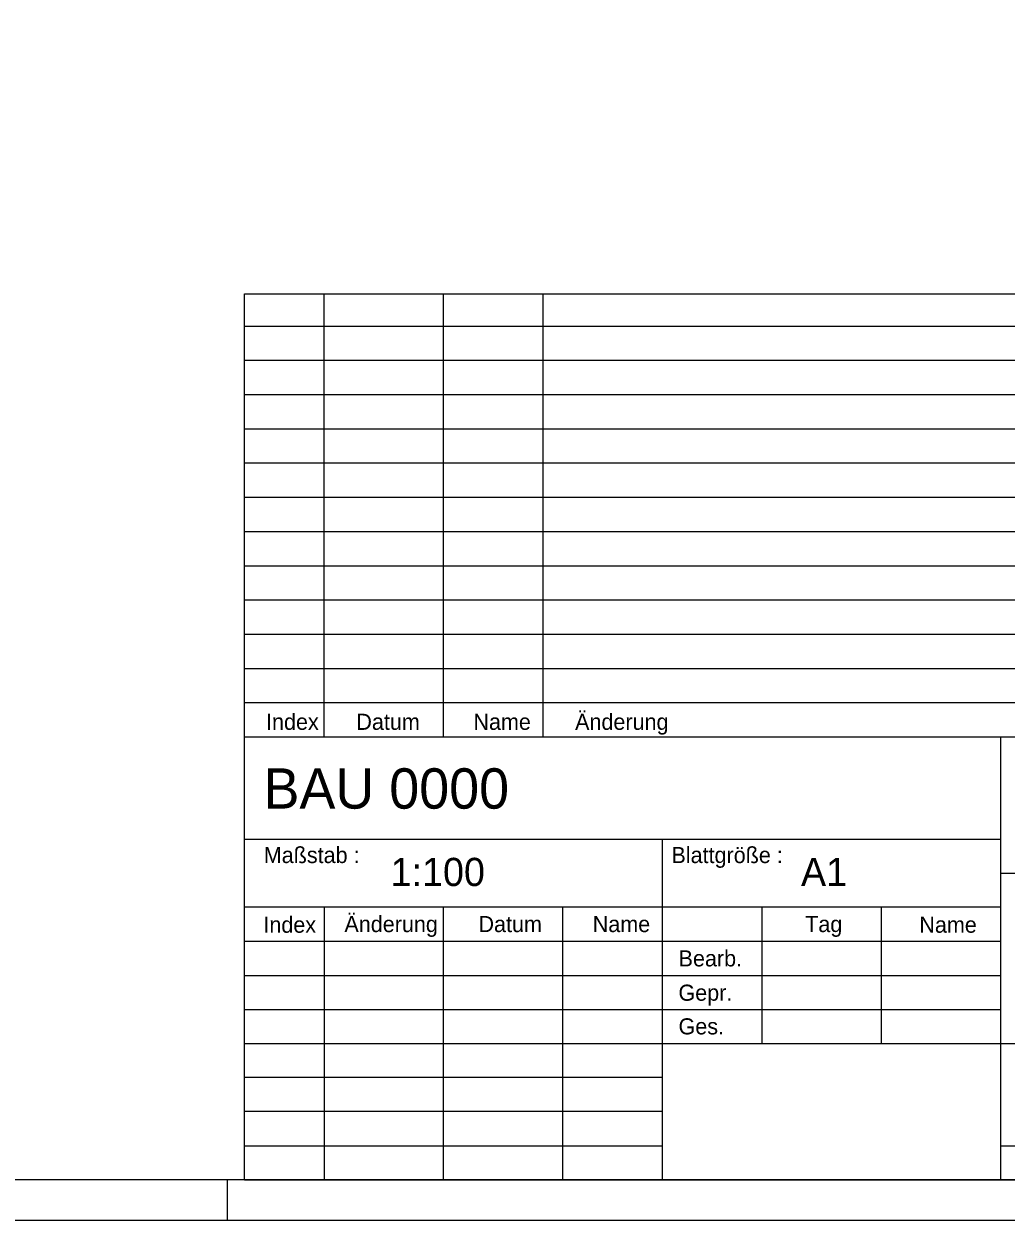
# Model space of a CAD drawing. Extents: x 0 to 84.1, y 0 to 59.4.
# Drawn here: x 63.08 to 75.27, y 0 to 14.85 of the extents above; entities that cross this region are included whole.
import ezdxf

# ---------------------------------------------------------------- set-up
doc = ezdxf.new("R2010")
doc.units = 0
doc.layers.add('90_Plankopf', color=7, linetype='Continuous')

msp = doc.modelspace()

# ---------------------------------------------------------------- linework, layer by layer
at = {"layer": '90_Plankopf'}
for p, q in [((65.812, 5.999), (65.812, 11.498)), ((65.812, 11.498), (83.6, 11.498)), ((66.8, 5.999), (66.8, 11.498)), ((68.283, 5.999), (68.283, 11.498)), ((69.518, 5.999), (69.518, 11.498)), ((65.812, 11.099), (83.6, 11.099)), ((65.812, 10.674), (83.6, 10.674)), ((65.812, 10.249), (83.6, 10.249)), ((65.812, 9.824), (83.6, 9.824)), ((65.812, 9.399), (83.6, 9.399)), ((65.812, 8.974), (83.6, 8.974)), ((65.812, 8.549), (83.6, 8.549)), ((65.812, 8.124), (83.6, 8.124)), ((65.812, 7.699), (83.6, 7.699)), ((65.812, 7.274), (83.6, 7.274)), ((65.812, 6.849), (83.6, 6.849)), ((65.812, 6.424), (83.6, 6.424)), ((65.812, 5.999), (83.6, 5.999)), ((65.812, 0.5), (65.812, 5.999)), ((65.812, 5.999), (83.6, 5.999)), ((75.2, 0.5), (75.2, 5.999)), ((65.812, 4.73), (75.2, 4.73)), ((71, 0.5), (71, 4.73)), ((75.2, 4.307), (83.6, 4.307)), ((65.812, 3.887), (75.2, 3.887)), ((66.8, 3.884), (66.8, 0.5)), ((68.283, 0.5), (68.283, 3.884)), ((69.765, 0.5), (69.765, 3.884)), ((72.235, 3.884), (72.235, 2.192)), ((73.718, 2.192), (73.718, 3.884)), ((65.812, 3.463), (75.2, 3.463)), ((65.812, 3.038), (75.2, 3.038)), ((65.812, 2.615), (75.2, 2.615)), ((65.812, 2.192), (75.2, 2.192)), ((65.812, 2.192), (75.2, 2.192)), ((71, 2.192), (75.2, 2.192)), ((75.2, 2.192), (83.6, 2.192)), ((71, 1.769), (65.812, 1.769)), ((71, 1.346), (65.812, 1.346)), ((65.812, 0.923), (71, 0.923)), ((75.2, 0.923), (83.6, 0.923)), ((65.6, 0), (65.6, 0.5)), ((83.6, 0.5), (65.812, 0.5)), ((65.812, 0.5), (71, 0.5)), ((66.98, 0.5), (83.6, 0.5)), ((66.98, 0.5), (83.6, 0.5))]:
    msp.add_line(p, q, dxfattribs=at)
for points in [[(0, 0), (84.1, 0), (84.1, 59.4), (0, 59.4)], [(2.5, 58.9), (83.6, 58.9), (83.6, 0.5), (2.5, 0.5)]]:
    msp.add_lwpolyline(points, close=True, dxfattribs=at)

# ---------------------------------------------------------------- texts
for s, height, p in [('Index', 0.2, (66.08, 6.086)), ('Datum', 0.2, (67.201, 6.086)), ('Name', 0.2, (68.654, 6.086)), ('Änderung', 0.2, (69.916, 6.086)), ('BAU 0000      ', 0.5, (66.049, 5.108)), ('Maßstab :', 0.2, (66.052, 4.432)), ('Blattgröße :', 0.19999, (71.112, 4.432)), ('1:100    ', 0.35, (67.626, 4.147)), ('A1       ', 0.35, (72.72, 4.147)), ('Index', 0.2, (66.047, 3.567)), ('Änderung', 0.2, (67.053, 3.575)), ('Datum', 0.2, (68.717, 3.575)), ('Name', 0.2, (70.135, 3.575)), ('Tag', 0.2, (72.772, 3.575)), ('Name', 0.2, (74.189, 3.567)), ('Bearb.', 0.2, (71.201, 3.149)), ('Gepr.', 0.2, (71.199, 2.723)), ('Ges.', 0.2, (71.2, 2.305))]:
    msp.add_text(s, height=height, dxfattribs=at).set_placement(p)

doc.saveas('drawing.dxf')
